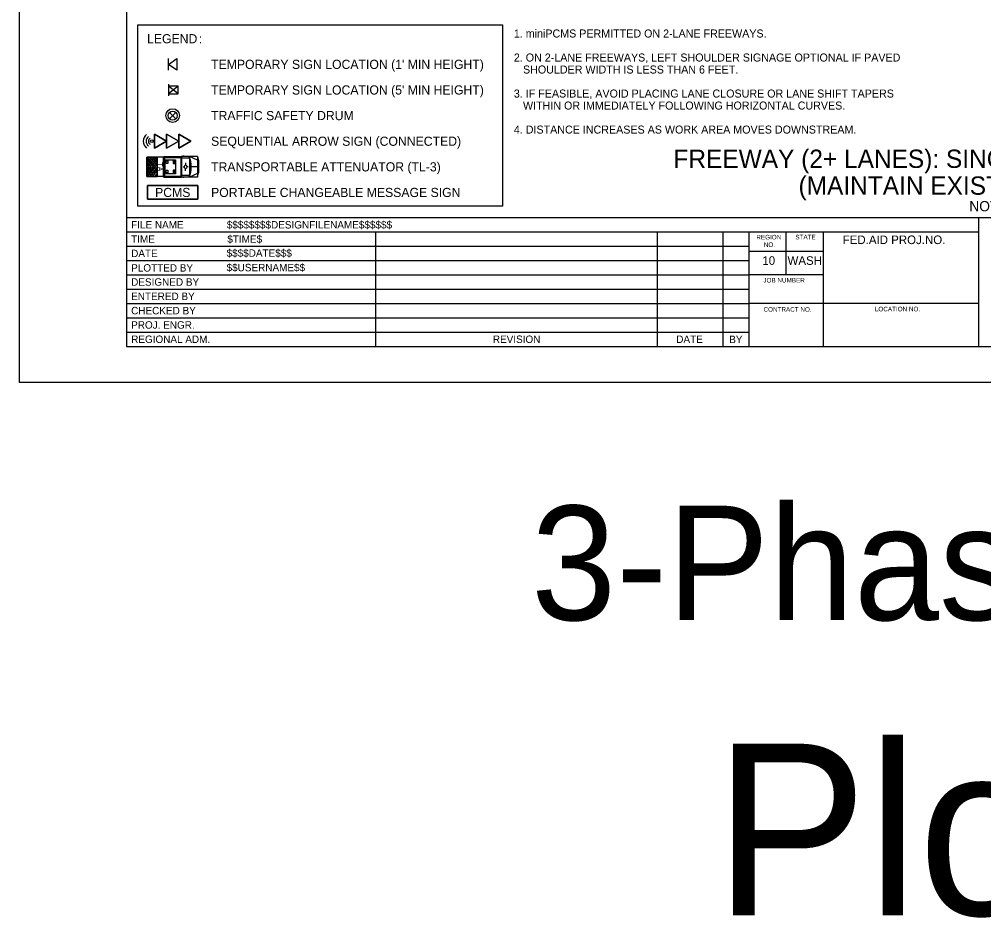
# Model space of a CAD drawing. Extents: x 99999 to 100116, y 99995 to 100013.
# Drawn here: x 99999.06 to 100007.5, y 99995.01 to 100002.86 of the extents above; entities that cross this region are included whole.
import ezdxf

# ---------------------------------------------------------------- set-up
doc = ezdxf.new("R2010")
doc.units = 0
for name, color, linetype in [('SH_DE_DetailHeading1Text', 7, 'Continuous'), ('SH_GI_GeneralNotesBodyText', 7, 'Continuous'), ('SH_GI_PlotLimits', 7, 'Continuous'), ('SH_GI_SheetBorder', 7, 'Continuous'), ('SH_GI_SheetLocationText', 7, 'Continuous'), ('SH_GI_SheetTextInCells', 7, 'Continuous'), ('SH_GI_TitleBlockText', 7, 'Continuous'), ('TR_WZ_PCMS', 7, 'Continuous'), ('TR_WZ_PortableSignMount5ftMinBlk-Wht', 7, 'Continuous'), ('TR_WZ_PortableSignMountBlk-Wht', 7, 'Continuous'), ('TR_WZ_SequentialArrowSign', 7, 'Continuous'), ('TR_WZ_TrafficSafetyDrum', 7, 'Continuous'), ('TR_WZ_TransportableAttenuator', 7, 'Continuous'), ('TR_WZ_WorkZoneTextCurrent', 7, 'Continuous')]:
    doc.layers.add(name, color=color, linetype=linetype)

msp = doc.modelspace()

# ---------------------------------------------------------------- linework, layer by layer
at = {"layer": 'SH_GI_PlotLimits'}
msp.add_lwpolyline([(99999.0625, 99999.6875), (100016.0625, 99999.6875), (100016.0625, 100010.6875), (99999.0625, 100010.6875)], close=True, dxfattribs=at)
at = {"layer": 'SH_GI_SheetBorder'}
for p, q in [((100000, 100010.375), (100000, 100000)), ((100000, 100001.1259), (100015.75, 100001.1259)), ((100007.4566, 100000), (100007.4566, 100001.1259)), ((100000, 100001.0008), (100007.4566, 100001.0008)), ((100002.179, 100001.0008), (100002.179, 100000)), ((100004.641, 100001.0008), (100004.641, 100000)), ((100005.2164, 100001.0008), (100005.2164, 100000)), ((100005.4451, 100001.0008), (100005.4451, 100000)), ((100005.7719, 100000.6255), (100005.7719, 100001.0008)), ((100006.0956, 100000), (100006.0956, 100001.0008)), ((100000, 100000.8757), (100002.1821, 100000.8757)), ((100002.1821, 100000.8757), (100005.4466, 100000.8757)), ((100006.0958, 100000.831), (100005.4466, 100000.831)), ((100000, 100000.7506), (100002.1821, 100000.7506)), ((100002.1821, 100000.7506), (100005.4466, 100000.7506)), ((100000, 100000.6255), (100005.4466, 100000.6255)), ((100006.0958, 100000.6255), (100005.4466, 100000.6255)), ((100000, 100000.5004), (100005.4466, 100000.5004)), ((100000, 100000.3753), (100005.4466, 100000.3753)), ((100007.4566, 100000.3753), (100005.4466, 100000.3753)), ((100000, 100000.2502), (100005.4466, 100000.2502)), ((100000, 100000.1251), (100005.4466, 100000.1251)), ((100000, 100000), (100015.75, 100000))]:
    msp.add_line(p, q, dxfattribs=at)
at = {"layer": 'TR_WZ_PCMS'}
for points in [[(100000.6241, 100001.4059), (100000.6241, 100001.2859), (100000.1841, 100001.2859), (100000.1841, 100001.4059), (100000.6241, 100001.4059)], [(100000.1841, 100001.4059), (100000.1841, 100001.2859), (100000.6241, 100001.2859), (100000.6241, 100001.4059), (100000.1841, 100001.4059)]]:
    msp.add_lwpolyline(points, dxfattribs=at)
at = {"layer": 'TR_WZ_PortableSignMount5ftMinBlk-Wht'}
for p, q in [((100000.3682, 100002.2919), (100000.3682, 100002.1919)), ((100000.4516, 100002.2094), (100000.3682, 100002.2744)), ((100000.4516, 100002.2744), (100000.3682, 100002.2094)), ((100000.4099, 100002.2419), (100000.4099, 100002.2419)), ((100000.41, 100002.2418), (100000.41, 100002.2418))]:
    msp.add_line(p, q, dxfattribs=at)
msp.add_lwpolyline([(100000.4516, 100002.2094), (100000.4516, 100002.2744), (100000.3682, 100002.2744), (100000.3682, 100002.2094)], close=True, dxfattribs=at)
at = {"layer": 'TR_WZ_PortableSignMountBlk-Wht'}
msp.add_line((100000.3682, 100002.416), (100000.3682, 100002.516), dxfattribs=at)
msp.add_lwpolyline([(100000.3682, 100002.4659), (100000.44, 100002.516), (100000.44, 100002.416)], close=True, dxfattribs=at)
at = {"layer": 'TR_WZ_SequentialArrowSign'}
for points in [[(100000.3508, 100001.7939), (100000.2441, 100001.7321), (100000.2441, 100001.8557), (100000.3508, 100001.7939)], [(100000.2441, 100001.8557), (100000.2441, 100001.7321), (100000.3508, 100001.7939), (100000.2441, 100001.8557)], [(100000.4575, 100001.7939), (100000.3508, 100001.7321), (100000.3508, 100001.7939), (100000.3508, 100001.8557), (100000.4575, 100001.7939)], [(100000.3508, 100001.8557), (100000.3508, 100001.7939), (100000.3508, 100001.7321), (100000.4575, 100001.7939), (100000.3508, 100001.8557)], [(100000.5641, 100001.7939), (100000.4575, 100001.7321), (100000.4575, 100001.7939), (100000.4575, 100001.8557), (100000.5641, 100001.7939)], [(100000.4575, 100001.8557), (100000.4575, 100001.7939), (100000.4575, 100001.7321), (100000.5641, 100001.7939), (100000.4575, 100001.8557)]]:
    msp.add_lwpolyline(points, dxfattribs=at)
msp.add_circle((100000.2216, 100001.7939), 0.0125, dxfattribs=at)
for radius, start, end in [(0.075, 127.32912, 232.67088), (0.05, 123.97816, 236.02184), (0.03, 117.15796, 242.84204)]:
    msp.add_arc((100000.2216, 100001.7939), radius, start, end, dxfattribs=at)
at = {"layer": 'TR_WZ_TrafficSafetyDrum'}
for p, q in [((100000.4324, 100002.0461), (100000.3758, 100001.9896)), ((100000.4324, 100001.9896), (100000.3758, 100002.0461))]:
    msp.add_line(p, q, dxfattribs=at)
for radius in [0.06, 0.06, 0.04]:
    msp.add_circle((100000.4041, 100002.0179), radius, dxfattribs=at)
at = {"layer": 'TR_WZ_TransportableAttenuator'}
for p, q in [((100000.1791, 100001.6385), (100000.2355, 100001.5706)), ((100000.1791, 100001.6167), (100000.1791, 100001.6385)), ((100000.2355, 100001.5706), (100000.1791, 100001.6385)), ((100000.1791, 100001.6385), (100000.1791, 100001.6167)), ((100000.2551, 100001.5701), (100000.185, 100001.6546)), ((100000.185, 100001.6546), (100000.2041, 100001.6546)), ((100000.185, 100001.6546), (100000.2551, 100001.5701)), ((100000.2041, 100001.6546), (100000.185, 100001.6546)), ((100000.2041, 100001.6546), (100000.2676, 100001.5776)), ((100000.2676, 100001.5776), (100000.2041, 100001.6546)), ((100000.2676, 100001.6025), (100000.2248, 100001.6546)), ((100000.2248, 100001.6546), (100000.2439, 100001.6546)), ((100000.2439, 100001.6546), (100000.2248, 100001.6546)), ((100000.2248, 100001.6546), (100000.2676, 100001.6025)), ((100000.2439, 100001.6546), (100000.2676, 100001.626)), ((100000.2676, 100001.626), (100000.2439, 100001.6546)), ((100000.2676, 100001.4857), (100000.2676, 100001.6546)), ((100000.3279, 100001.6546), (100000.2676, 100001.6546)), ((100000.3208, 100001.6515), (100000.3208, 100001.4884)), ((100000.3241, 100001.657), (100000.3274, 100001.657)), ((100000.3274, 100001.657), (100000.3274, 100001.4829)), ((100000.3279, 100001.6599), (100000.4803, 100001.6599)), ((100000.3279, 100001.6599), (100000.3279, 100001.4799)), ((100000.3279, 100001.6543), (100000.3279, 100001.4857)), ((100000.3323, 100001.6528), (100000.3323, 100001.4871)), ((100000.3323, 100001.6528), (100000.476, 100001.6528)), ((100000.476, 100001.6528), (100000.476, 100001.4871)), ((100000.4803, 100001.6599), (100000.4803, 100001.4799)), ((100000.4824, 100001.6599), (100000.4824, 100001.4799)), ((100000.6223, 100001.6599), (100000.4824, 100001.6599)), ((100000.551, 100001.646), (100000.4824, 100001.646)), ((100000.5014, 100001.6625), (100000.493, 100001.6625)), ((100000.551, 100001.6599), (100000.5421, 100001.646)), ((100000.551, 100001.6599), (100000.551, 100001.4799)), ((100000.5523, 100001.6599), (100000.5523, 100001.4799)), ((100000.6223, 100001.627), (100000.5523, 100001.6599)), ((100000.6223, 100001.6599), (100000.6223, 100001.4799)), ((100000.6223, 100001.6599), (100000.6291, 100001.6236)), ((100000.2174, 100001.5709), (100000.1791, 100001.6167)), ((100000.1791, 100001.6167), (100000.2174, 100001.5709)), ((100000.1791, 100001.5935), (100000.1987, 100001.5702)), ((100000.1791, 100001.5467), (100000.1791, 100001.5935)), ((100000.1987, 100001.5702), (100000.1791, 100001.5935)), ((100000.1791, 100001.5935), (100000.1791, 100001.5467)), ((100000.1791, 100001.5248), (100000.2174, 100001.5709)), ((100000.2174, 100001.5709), (100000.1791, 100001.5248)), ((100000.2355, 100001.5706), (100000.1791, 100001.5027)), ((100000.1791, 100001.5027), (100000.2355, 100001.5706)), ((100000.1987, 100001.5702), (100000.1791, 100001.5467)), ((100000.1791, 100001.5467), (100000.1987, 100001.5702)), ((100000.1849, 100001.4855), (100000.2551, 100001.5701)), ((100000.2551, 100001.5701), (100000.1849, 100001.4855)), ((100000.2676, 100001.5625), (100000.2037, 100001.4855)), ((100000.2037, 100001.4855), (100000.2676, 100001.5625)), ((100000.2676, 100001.626), (100000.2676, 100001.6025)), ((100000.2676, 100001.6025), (100000.2676, 100001.626)), ((100000.2676, 100001.5776), (100000.2676, 100001.5625)), ((100000.2676, 100001.5625), (100000.2676, 100001.5776)), ((100000.3208, 100001.5826), (100000.3274, 100001.5793)), ((100000.3208, 100001.5573), (100000.3274, 100001.5607)), ((100000.3226, 100001.57), (100000.3257, 100001.57)), ((100000.3241, 100001.5725), (100000.3241, 100001.5674)), ((100000.4951, 100001.5701), (100000.5045, 100001.57)), ((100000.507, 100001.5696), (100000.507, 100001.5696)), ((100000.5175, 100001.6056), (100000.5175, 100001.5911)), ((100000.5398, 100001.5701), (100000.5305, 100001.57)), ((100000.6223, 100001.57), (100000.566, 100001.57)), ((100000.6291, 100001.6236), (100000.6291, 100001.5163)), ((100000.1791, 100001.5027), (100000.1791, 100001.5248)), ((100000.1791, 100001.5248), (100000.1791, 100001.5027)), ((100000.2037, 100001.4855), (100000.1849, 100001.4855)), ((100000.1849, 100001.4855), (100000.2037, 100001.4855)), ((100000.2243, 100001.4855), (100000.2676, 100001.5376)), ((100000.2676, 100001.5376), (100000.2243, 100001.4855)), ((100000.2446, 100001.4855), (100000.2243, 100001.4855)), ((100000.2243, 100001.4855), (100000.2446, 100001.4855)), ((100000.2676, 100001.5128), (100000.2446, 100001.4855)), ((100000.2446, 100001.4855), (100000.2676, 100001.5128)), ((100000.2676, 100001.5376), (100000.2676, 100001.5128)), ((100000.2676, 100001.5128), (100000.2676, 100001.5376)), ((100000.3279, 100001.4857), (100000.2676, 100001.4857)), ((100000.3241, 100001.4829), (100000.3274, 100001.4829)), ((100000.3279, 100001.4799), (100000.4803, 100001.4799)), ((100000.3323, 100001.4871), (100000.476, 100001.4871)), ((100000.551, 100001.4939), (100000.4824, 100001.4939)), ((100000.6223, 100001.4799), (100000.4824, 100001.4799)), ((100000.5014, 100001.4774), (100000.493, 100001.4774)), ((100000.5175, 100001.5343), (100000.5175, 100001.5488)), ((100000.5437, 100001.4939), (100000.551, 100001.4799)), ((100000.6223, 100001.5129), (100000.5523, 100001.4799)), ((100000.6223, 100001.4799), (100000.6291, 100001.5163))]:
    msp.add_line(p, q, dxfattribs=at)
for points in [[(100000.2676, 100001.4855), (100000.1791, 100001.4855), (100000.1791, 100001.6546), (100000.2676, 100001.6546)], [(100000.3398, 100001.63), (100000.4298, 100001.63), (100000.4298, 100001.51), (100000.3398, 100001.51)], [(100000.3473, 100001.6225), (100000.3623, 100001.6225), (100000.3623, 100001.6), (100000.3473, 100001.6)], [(100000.4223, 100001.6225), (100000.4073, 100001.6225), (100000.4073, 100001.6), (100000.4223, 100001.6)], [(100000.3473, 100001.54), (100000.3623, 100001.54), (100000.3623, 100001.5175), (100000.3473, 100001.5175)], [(100000.4223, 100001.54), (100000.4073, 100001.54), (100000.4073, 100001.5175), (100000.4223, 100001.5175)]]:
    msp.add_lwpolyline(points, close=True, dxfattribs=at)
msp.add_lwpolyline([(100000.2676, 100001.6546), (100000.1791, 100001.6546), (100000.1791, 100001.4855), (100000.2676, 100001.4857)], dxfattribs=at)
for centre, major_axis, start_param, end_param in [((100000.3241, 100001.6515), (0, 0.00549), 6.283185, 7.853982), ((100000.4523, 100001.5699), (0, 0.1889), 4.215852, 5.209111), ((100000.3241, 100001.4884), (0, -0.00549), 4.712389, 6.283185)]:
    msp.add_ellipse(centre, major_axis=major_axis, ratio=0.60201, start_param=start_param, end_param=end_param, dxfattribs=at)
for centre, major_axis in [((100000.3241, 100001.5699), (0, -0.00254)), ((100000.5175, 100001.5699), (0, -0.0173))]:
    msp.add_ellipse(centre, major_axis=major_axis, ratio=0.60201, dxfattribs=at)
at = {"layer": 'TR_WZ_WorkZoneTextCurrent'}
msp.add_lwpolyline([(100000.1, 100002.8099), (100003.2886, 100002.8099), (100003.2886, 100001.2259), (100000.1, 100001.2259)], close=True, dxfattribs=at)

# ---------------------------------------------------------------- texts
at = {"layer": 'SH_DE_DetailHeading1Text'}
for s, height, p in [('FREEWAY (2+ LANES): SINGLE RIGHT LANE CLOSURE', 0.16, (100004.7843, 100001.5606)), ('(MAINTAIN EXISTING SPEED LIMIT)', 0.16, (100005.8785, 100001.3259)), ('NOT TO SCALE', 0.09, (100007.3725, 100001.1809))]:
    msp.add_text(s, height=height, rotation=360, dxfattribs=at).set_placement(p)
at = {"layer": 'SH_GI_GeneralNotesBodyText'}
for s, p in [('1. miniPCMS PERMITTED ON 2-LANE FREEWAYS.', (100003.3886, 100002.7006)), ('2. ON 2-LANE FREEWAYS, LEFT SHOULDER SIGNAGE OPTIONAL IF PAVED ', (100003.3886, 100002.4906)), ('SHOULDER WIDTH IS LESS THAN 6 FEET.', (100003.4686, 100002.3856)), ('3. IF FEASIBLE, AVOID PLACING LANE CLOSURE OR LANE SHIFT TAPERS ', (100003.3886, 100002.1756)), ('WITHIN OR IMMEDIATELY FOLLOWING HORIZONTAL CURVES.', (100003.4686, 100002.0706)), ('4. DISTANCE INCREASES AS WORK AREA MOVES DOWNSTREAM.', (100003.3886, 100001.8606))]:
    msp.add_text(s, height=0.07, rotation=360, dxfattribs=at).set_placement(p)
at = {"layer": 'SH_GI_SheetLocationText'}
for s, height, p in [('3-Phase PCMS', 1, (100003.5395, 99997.6071)), ('Plot 1', 1.5, (100005.1422, 99995.0267))]:
    msp.add_text(s, height=height, dxfattribs=at).set_placement(p)
at = {"layer": 'SH_GI_SheetTextInCells'}
for s, height, p in [('FILE NAME', 0.06505, (100000.041, 100001.0308)), ('TIME', 0.06505, (100000.041, 100000.9057)), ('REGION', 0.04003, (100005.5099, 100000.9352)), ('STATE', 0.04003, (100005.8511, 100000.9357)), ('FED.AID PROJ.NO.', 0.07506, (100006.2652, 100000.8945)), ('NO.', 0.04003, (100005.5752, 100000.869)), ('DATE', 0.06505, (100000.041, 100000.7806)), ('PLOTTED BY', 0.06505, (100000.041, 100000.6538)), ('10', 0.07506, (100005.5621, 100000.7131)), ('WASH', 0.07506, (100005.7826, 100000.7131)), ('DESIGNED BY', 0.065052, (100000.041, 100000.5304)), ('JOB NUMBER', 0.04003, (100005.5712, 100000.5587)), ('ENTERED BY', 0.06505, (100000.041, 100000.4053)), ('CHECKED BY', 0.06505, (100000.041, 100000.2802)), ('CONTRACT NO.', 0.040032, (100005.5725, 100000.3037)), ('LOCATION NO.', 0.040032, (100006.5465, 100000.3067)), ('PROJ. ENGR.', 0.065052, (100000.041, 100000.1551)), ('REGIONAL ADM.', 0.065052, (100000.041, 100000.03)), ('REVISION', 0.06505, (100003.2048, 100000.03)), ('DATE', 0.06505, (100004.8091, 100000.03)), ('BY', 0.06505, (100005.2725, 100000.0285))]:
    msp.add_text(s, height=height, dxfattribs=at).set_placement(p)
at = {"layer": 'SH_GI_TitleBlockText'}
for s, height, p in [('$$$$$$$$DESIGNFILENAME$$$$$$', 0.065052, (100000.8775, 100001.0308)), ('$TIME$', 0.06505, (100000.882, 100000.9059)), ('$$$$DATE$$$', 0.065052, (100000.8759, 100000.7835)), ('$$USERNAME$$', 0.065052, (100000.8759, 100000.6567))]:
    msp.add_text(s, height=height, dxfattribs=at).set_placement(p)
at = {"layer": 'TR_WZ_PCMS'}
msp.add_text('PCMS', height=0.08, rotation=360, dxfattribs=at).set_placement((100000.2502, 100001.3059))
at = {"layer": 'TR_WZ_TransportableAttenuator'}
msp.add_text('TA', height=0.045, rotation=269.99999, dxfattribs=at).set_placement((100000.2717, 100001.6094))
at = {"layer": 'TR_WZ_WorkZoneTextCurrent'}
for s, p in [('LEGEND', (100000.18, 100002.6499)), (':', (100000.6328, 100002.6499)), ("TEMPORARY SIGN LOCATION (1' MIN HEIGHT)", (100000.74, 100002.4259)), ("TEMPORARY SIGN LOCATION (5' MIN HEIGHT)", (100000.74, 100002.2019)), ('TRAFFIC SAFETY DRUM', (100000.74, 100001.9779)), ('SEQUENTIAL ARROW SIGN (CONNECTED)', (100000.74, 100001.7539)), ('TRANSPORTABLE ATTENUATOR (TL-3)', (100000.74, 100001.5299)), ('PORTABLE CHANGEABLE MESSAGE SIGN', (100000.74, 100001.3059))]:
    msp.add_text(s, height=0.08, rotation=360, dxfattribs=at).set_placement(p)

doc.saveas('drawing.dxf')
